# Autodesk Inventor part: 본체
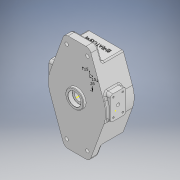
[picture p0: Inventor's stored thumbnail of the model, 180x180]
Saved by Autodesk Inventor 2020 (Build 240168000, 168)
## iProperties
Created: 2023-11
Part Number: 본체
Material: 일반
Document SubType Name: Modeling
Designer: CAD16
Density: 1 g/cm^3
Appearance: 기본값
Author: CAD16
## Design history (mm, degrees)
sketch "스케치1"
  geometry: L1 (-17.315, 94)-(17.315, 94); L2 (0, 94)-(0, 0); L3 (51.683, 18.811)-(26.711, 87.42); L4 (-51.683, 18.811)-(-26.711, 87.42); L5 (-55, 0)-(55, 0); L6 (51.683, -18.811)-(26.711, -87.42); L7 (-51.683, -18.811)-(-26.711, -87.42); L8 (-17.315, -94)-(17.315, -94); A1 r 55 centre (0, 0) between (-51.683, 18.811) and (51.683, 18.811); A2 r 10 centre (17.315, 84) between (26.711, 87.42) and (17.315, 94); A3 r 10 centre (-17.315, 84) between (-17.315, 94) and (-26.711, 87.42); A4 r 10 centre (-17.315, -84) between (-26.711, -87.42) and (-17.315, -94); A5 r 10 centre (17.315, -84) between (17.315, -94) and (26.711, -87.42); 7 further points
  constraints: 16 end point, 12 point on circle, 9 tangent, 8 point on line, 6 symmetric about line, 5 centre point, 2 equal radius, 2 horizontal, 2 midpoint, 1 coincident, 1 vertical
  dimensions: "d0" = 94 distance from line of point (0, 0) L1; "d1" = 110 diameter of A1; "d4" = 40 deg angle of L3 L4; "d119" = 10 radius of A2; "d120" = 10 radius of A3
extrude "돌출1" new body sketch "스케치1" distance "d5" = 15; taper "d6" = 0 deg
sketch "스케치2"
  geometry: L1 (-26.711, -87.42)-(-51.683, -18.811) reference; L2 (17.315, -94)-(-17.315, -94) reference; L3 (51.683, -18.811)-(26.711, -87.42) reference; L4 (26.711, 87.42)-(51.683, 18.811) reference; L5 (-17.315, 94)-(17.315, 94) reference; L6 (-51.683, 18.811)-(-26.711, 87.42) reference; L7 (-51.683, 18.811)-(-24.317, 94) reference; L8 (-33.78, 68)-(33.78, 68); L9 (24.317, 94)-(51.683, 18.811) reference; L10 (-24.317, -94)-(-51.683, -18.811) reference; L11 (-33.78, -68)-(33.78, -68); L12 (51.683, -18.811)-(24.317, -94) reference; L13 (24.317, 94)-(51.683, 18.811) reference; L14 (51.683, -18.811)-(24.317, -94) reference; L15 (-24.317, -94)-(-51.683, -18.811) reference; L16 (-51.683, 18.811)-(-24.317, 94) reference; L17 (-33.78, 68)-(-51.683, 18.811); L18 (-51.683, -18.811)-(-33.78, -68); L19 (33.78, -68)-(51.683, -18.811); L20 (51.683, 18.811)-(33.78, 68); C1 r 55 at (0, 0); A1 r 55 centre (0, 0) between (-51.683, 18.811) and (-51.683, -18.811) reference; A2 r 55 centre (0, 0) between (51.683, -18.811) and (51.683, 18.811) reference; A3 r 55 centre (0, 0) between (51.683, -18.811) and (51.683, 18.811) reference; A4 r 55 centre (0, 0) between (-51.683, 18.811) and (-51.683, -18.811) reference; A5 r 55 centre (0, 0) between (51.683, -18.811) and (51.683, 18.811) reference; A6 r 10 centre (17.315, 84) between (26.711, 87.42) and (17.315, 94) reference; A7 r 10 centre (-17.315, 84) between (-17.315, 94) and (-26.711, 87.42) reference; A8 r 10 centre (-17.315, -84) between (-26.711, -87.42) and (-17.315, -94) reference; A9 r 10 centre (17.315, -84) between (17.315, -94) and (26.711, -87.42) reference; 5 further points
  constraints: 12 end point, 4 point on line, 4 tangent, 3 collinear, 2 horizontal, 1 centre point, 1 coincident
  dimensions: "d7" = 68 distance from line of point (0, 0) L8; "d8" = 68 distance from line of point (0, 0) L11; "d9" = 110 diameter of C1
extrude "돌출2" join sketch "스케치2" distance "d10" = 40; taper "d11" = 0 deg
node "작업 평면1"
sketch "스케치13"
  geometry: L1 (0, 0)-(25, 0); L2 (25, 0)-(25, 61); L3 (25, 0)-(25, -61); C1 r 8 at (0, 0) reference; 1 further point
  constraints: 6 end point, 1 horizontal, 1 perpendicular, 1 vertical
  dimensions: "d34" = 25 distance of L1.start L1.end; "d35" = 61 distance of L1.end L2.end; "d36" = 61 distance of L1.end L3.end
hole "구멍1" sketch "스케치13" at (25, 61), (25, -61) diameter "d37" = 4.917; stored, may be unused: countersink angle "d41" = 90 deg, drill point angle "d43" = 120 deg; dims "d38" = 12, "d39" = 4, "d40" = 2, "d42" = 14
fillet "모깎기4" dims "d112" = 3
fillet "모깎기5" dims "d113" = 3
sketch "스케치21"
  geometry: L1 (0, 37)-(63.358, 37) reference; 3 further points
  constraints: 1 midpoint, 1 vertical alignment, 1 other
  dimensions: "d115" = 15 distance from line of L1 point (31.679, 22)
feature "엠보싱1" sketch "스케치21" dims "d0" = 94, "d1" = 110, "d4" = 40 deg, "d116" = 0.5, "d117" = 0, "d119" = 10, "d120" = 10
sketch "스케치25"
  geometry: 1 further point
sketch "스케치26"
  geometry: L1 (0, 0)-(0, 9); C1 r 40 at (0, 9)
  constraints: 2 end point, 1 centre point, 1 coincident, 1 vertical
  dimensions: "d125" = 9 distance of L1.start L1.end; "d126" = 80 diameter of C1
extrude "돌출11" cut sketch "스케치26" distance "d127" = 30; taper "d128" = 0 deg
sketch "스케치27"
  geometry: C1 r 17.5 at (0, 0); 1 further point
  constraints: 1 centre point, 1 coincident
  dimensions: "d129" = 35 diameter of C1
extrude "돌출12" join sketch "스케치27" distance "d130" = 5; taper "d131" = 0 deg
chamfer "모따기2" distance "d132" = 1; stored, may be unused: second distance "d133" = 2, angle "d134" = 45 deg
sketch "스케치28"
  geometry: C1 r 12.5 at (0, 0); 1 further point
  constraints: 1 centre point, 1 coincident
  dimensions: "d135" = 25 diameter of C1
extrude "돌출13" cut sketch "스케치28" distance "d136" = 8.4; taper "d137" = 0 deg
sketch "스케치29"
  geometry: 1 further point
sketch "스케치30"
  geometry: C1 r 12.5 at (0, -9) reference; C2 r 10 at (0, -9); 1 further point
  constraints: 1 centre point, 1 coincident
  dimensions: "d138" = 20 diameter of C2
extrude "돌출14" cut sketch "스케치30" distance "d139" = 10; taper "d140" = 0 deg
sketch "스케치31"
  geometry: C1 r 8 at (0, 0); 1 further point
  constraints: 1 centre point, 1 coincident
  dimensions: "d141" = 16 diameter of C1
extrude "돌출15" cut sketch "스케치31" extent not by distance; stored distance "d142" = 10; taper "d143" = 0 deg
node "작업 평면2"
sketch "스케치34"
  geometry: L1 (63.459, -40)-(58.542, -40) reference; L2 (56.5, -40)-(52.4, -40); L3 (52.4, -40)-(52.4, -38.1); L4 (52.9, -37.6)-(56, -37.6); L5 (56.5, -38.1)-(56.5, -40); L6 (49, -40)-(-31, -40) reference; L7 (9, -40)-(9, -28.722); A1 r 0.5 centre (56, -38.1) between (56.5, -38.1) and (56, -37.6); A2 r 0.5 centre (52.9, -38.1) between (52.9, -37.6) and (52.4, -38.1); 3 further points
  constraints: 10 end point, 5 point on line, 4 point on circle, 4 tangent, 2 centre point, 2 parallel, 1 equal radius, 1 horizontal, 1 midpoint, 1 perpendicular, 1 vertical
  dimensions: "d145" = 4.1 distance of point (52.4, -37.6) point (56.5, -37.6); "d146" = 2.4 distance of point (56.5, -37.6) L2.start; "d147" = 0.5 radius of A1; "d148" = 47.5 distance from line of L2.start L7
revolve "회전3" sketch "스케치34" stored, may be unused: angle "d149" = 90 deg
sketch "스케치35"
  geometry: L1 (-26.702, 6)-(-22.517, 6); L2 (22.517, 6)-(26.702, 6); L3 (-26.702, -6)-(-25.515, -6); L4 (25.515, -6)-(26.702, -6); L5 (-28.373, -6)-(-26.108, -6); C1 r 40 at (0, 0) reference; C2 r 43.4 at (0, 0) reference; C3 r 10 at (0, -9) reference; C4 r 47.5 at (0, 0) reference; A1 r 29 centre (0, 0) between (28.68, -4.296) and (28.68, 4.296); A2 r 29 centre (0, 0) between (-28.68, 4.296) and (-28.68, -4.296); A3 r 24 centre (0, -9) between (-20.785, 3) and (-23.552, -4.385); A4 r 24 centre (0, -9) between (23.552, -4.385) and (20.785, 3); A5 r 2 centre (26.702, 4) between (28.68, 4.296) and (26.702, 6); A6 r 2 centre (26.702, -4) between (26.702, -6) and (28.68, -4.296); A7 r 2 centre (-26.702, 4) between (-26.702, 6) and (-28.68, 4.296); A8 r 2 centre (-22.517, 4) between (-20.785, 3) and (-22.517, 6); A9 r 2 centre (22.517, 4) between (22.517, 6) and (20.785, 3); A10 r 2 centre (-25.515, -4) between (-25.515, -6) and (-23.552, -4.385); A11 r 2 centre (-26.702, -4) between (-28.68, -4.296) and (-26.702, -6); A12 r 2 centre (25.515, -4) between (23.552, -4.385) and (25.515, -6); 9 further points
  constraints: 32 point on circle, 17 tangent, 12 centre point, 10 end point, 9 point on line, 3 equal radius, 3 horizontal, 2 coincident, 2 parallel, 1 midpoint, 1 vertical alignment
  dimensions: "d156" = 2 radius of A5; "d157" = 2 radius of A7 (derived); "d158" = 2 radius of A9 (derived); "d159" = 2 radius of A10 (derived); "d160" = 2 radius of A11 (derived); "d161" = 24 radius of A4; "d162" = 29 radius of A1; "d163" = 29 radius of A2; "d164" = 24 radius of A3; "d165" = 25.5147 horizontal distance of point (0, -9) A10.centre; "d166" = 26.70206 horizontal distance of point (0, -9) A7.centre
extrude "돌출16" cut sketch "스케치35" distance "d167" = 12; taper "d168" = 0 deg
node "작업 평면3"
sketch "스케치36"
  geometry: L1 (25.483, 10)-(-10.517, 10); L2 (-15.517, 5)-(-15.517, -15); L3 (-10.517, -20)-(25.483, -20); L4 (30.483, -15)-(30.483, 5); L5 (30.483, 10)-(-15.517, -20); L6 (-15.517, 10)-(30.483, -20); L7 (-16.5, 20)-(16.5, 20) reference; A1 r 5 centre (25.483, 5) between (30.483, 5) and (25.483, 10); A2 r 5 centre (25.483, -15) between (25.483, -20) and (30.483, -15); A3 r 5 centre (-10.517, -15) between (-15.517, -15) and (-10.517, -20); A4 r 5 centre (-10.517, 5) between (-10.517, 10) and (-15.517, 5); 2 further points
  constraints: 12 end point, 8 point on circle, 8 point on line, 8 tangent, 4 centre point, 3 equal radius, 2 midpoint, 2 parallel, 1 horizontal, 1 perpendicular
  dimensions: "d172" = 30 distance of L6.start L5.end; "d173" = 46 distance of L5.end L6.end; "d175" = 25 distance from line of L7 point (7.483, -5); "d176" = 9 distance of point (0, 0) point (7.483, -5); "d179" = 5 radius of A1 (derived)
extrude "돌출17" join sketch "스케치36" stored distance "d177" = 12; taper "d178" = 0 deg
sketch "스케치37"
  geometry: 1 further point
sketch "스케치38"
  geometry: 1 further point
sketch "스케치39"
  geometry: L1 (-10, 25.483)-(-10, -10.517) reference; L2 (-10, 7.483)-(5, 7.483); L3 (15, 30.483)-(-5, 30.483) reference; L4 (5, 30.483)-(5, 4.615); L5 (10, 4.615)-(-2, 4.615) reference; C1 r 3 at (5, 7.483); 1 further point
  constraints: 4 end point, 2 midpoint, 2 point on line, 1 centre point, 1 coincident, 1 horizontal, 1 vertical
  dimensions: "d180" = 6 diameter of C1
extrude "돌출18" cut sketch "스케치39" stored distance "d181" = 12; taper "d182" = 0 deg
sketch "스케치40"
  geometry: L1 (10, 49)-(10, -31) reference; L2 (10, 13.296)-(-2, 13.296) reference; L3 (5, 7.483)-(5, 24.483); L4 (5, 24.483)-(14, 24.483); L5 (40, 18.811)-(-15, 18.811) reference; L6 (5, 24.483)-(-4, 24.483); L7 (-10, 25.483)-(-10, -10.517) reference; C1 r 3 at (5, 7.483) reference; 1 further point
  constraints: 6 end point, 1 parallel, 1 perpendicular, 1 vertical
  dimensions: "d183" = 17 distance of L3.start L3.end; "d184" = 9 distance of L3.end L4.end; "d185" = 9 distance of L3.end L6.end
hole "구멍5" sketch "스케치40" at (14, 24.483), (-4, 24.483) diameter "d186" = 3.242; stored, may be unused: countersink angle "d190" = 90 deg, drill point angle "d192" = 120 deg; dims "d187" = 8, "d188" = 4, "d189" = 2, "d191" = 10
sketch "스케치41"
  geometry: L1 (5, 7.483)-(20, 7.483); L2 (20, -10.517)-(20, 25.483) reference; L3 (5, 7.483)-(5, -9.517); L4 (5, -9.517)-(14, -9.517); L5 (5, -9.517)-(-4, -9.517); C1 r 3 at (5, 7.483) reference; 1 further point
  constraints: 8 end point, 1 horizontal, 1 midpoint, 1 perpendicular, 1 vertical
  dimensions: "d193" = 9 distance of L3.end L5.end; "d194" = 9 distance of L3.end L4.end; "d195" = 17 distance of L1.start L3.end
hole "구멍6" sketch "스케치41" at (-4, -9.517), (14, -9.517) diameter "d196" = 3.242; stored, may be unused: countersink angle "d200" = 90 deg, drill point angle "d202" = 120 deg; dims "d197" = 8, "d198" = 4, "d199" = 2, "d201" = 10
fillet "모깎기9" dims "d203" = 3
sketch "스케치42"
  geometry: L1 (0, -9)-(0, 17); L2 (0, 17)-(15, 17); L3 (0, 17)-(-15, 17)
  constraints: 6 end point, 1 horizontal, 1 perpendicular, 1 vertical
  dimensions: "d204" = 26 distance of L1.start L1.end; "d205" = 15 distance of L1.end L2.end; "d206" = 15 distance of L1.end L3.end
fillet "모깎기10" dims "d207" = 2
sketch "스케치43"
  geometry: L1 (0, 0)-(0, 79); L2 (0, 79)-(20, 79); L3 (0, 79)-(-20, 79); C1 r 12.5 at (0, 0) reference; 1 further point
  constraints: 6 end point, 2 horizontal, 1 vertical
  dimensions: "d208" = 79 distance of L1.start L1.end; "d209" = 20 distance of L1.end L2.end; "d210" = 20 distance of L1.end L3.end
hole "구멍7" sketch "스케치43" at (-20, 79), (20, 79) diameter "d211" = 6.6; stored, may be unused: countersink angle "d215" = 90 deg, drill point angle "d217" = 120 deg; dims "d212" = 8, "d213" = 11, "d214" = 6.6, "d216" = 10
sketch "스케치44"
  geometry: L1 (12.731, 20)-(12.5, 19.6); L2 (12.5, 20)-(12.5, 11.6) reference; L3 (-16.5, 20)-(16.5, 20) reference; L4 (12.5, 20)-(12.5, 19.6); L5 (12.5, 20)-(12.731, 20); L6 (0, 20)-(0, 13.232); 1 further point
  constraints: 8 end point, 2 perpendicular, 2 point on line, 1 midpoint, 1 vertical
  dimensions: "d218" = 0.4 distance of L1.end L2.start; "d219" = 30 deg angle of L2 L1
revolve "회전4" sketch "스케치44" stored, may be unused: angle "d220" = 90 deg
fillet "모깎기11" dims "d221" = 0.2
node "솔리드1"
mirror "미러2"
mirror "미러6"
mirror "미러7"
node "투영된 루프1"
feature "A9D066F2-1C7D-4E18-AEED-F7BC21143FA4" dims "d211" = 6.6, "d212" = 8, "d213" = 11, "d214" = 6.6, "d215" = 90 deg, "d216" = 10, "d217" = 120 deg
other parameters: "d27" = 59, "d65" = 58, "d66" = 48, "d68" = 12, "d144" = 59, "d150" = 58, "d153" = 3, "d154" = 12, "d155" = 48, "d169" = 59
